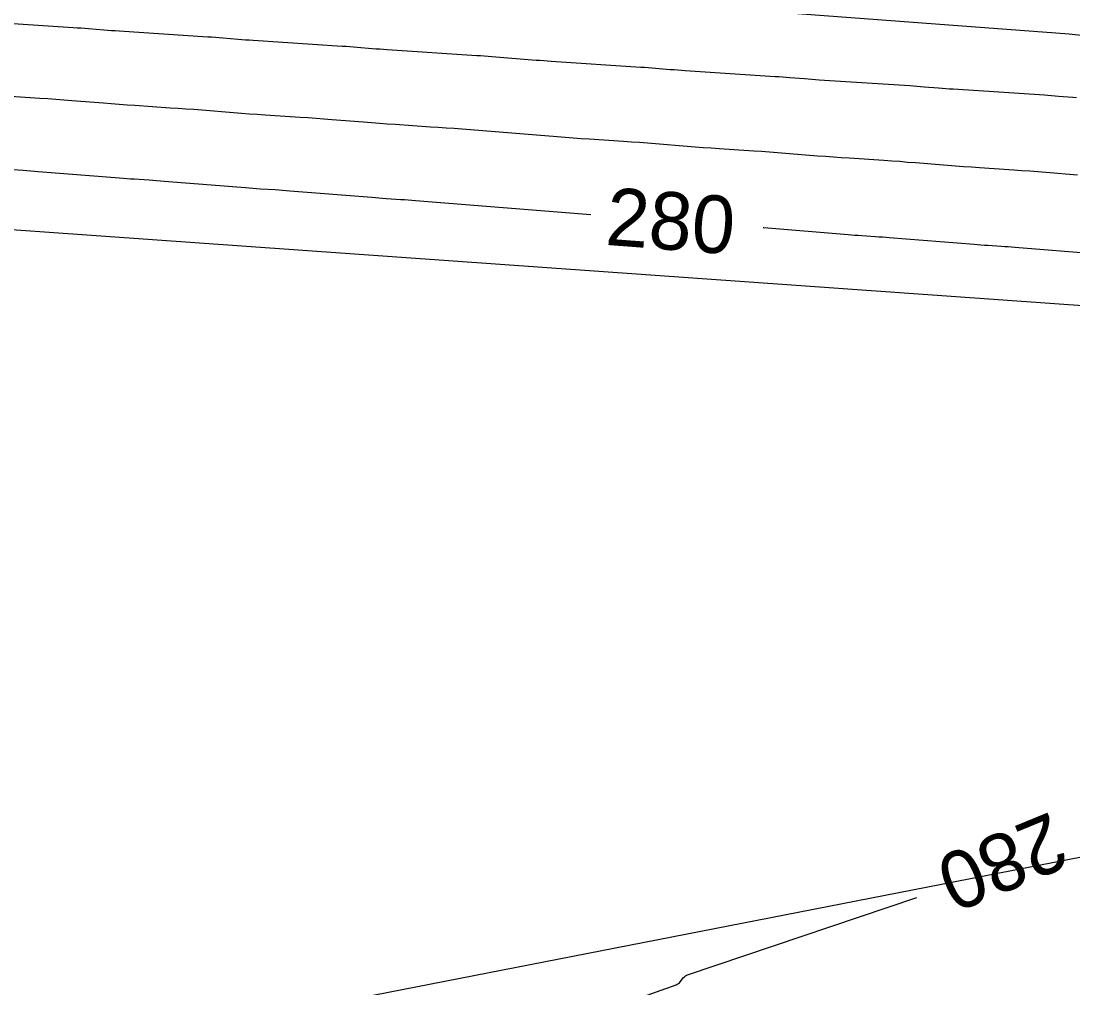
# Model space of a CAD drawing. Extents: x 1574966 to 1597594, y 720505 to 737840.
# Drawn here: x 1577690.4 to 1577800, y 724330.5 to 724431.3 of the extents above; entities that cross this region are included whole.
import ezdxf

# ---------------------------------------------------------------- set-up
doc = ezdxf.new("R2010")
doc.units = 0
for name, color, linetype in [('R_Contour Annot', 7, 'Continuous'), ('R_Contours', 7, 'Continuous'), ('S_BREAKLINE', 7, 'Continuous'), ('S_STREAM', 7, 'Continuous')]:
    doc.layers.add(name, color=color, linetype=linetype)

msp = doc.modelspace()

# ---------------------------------------------------------------- linework, layer by layer
at = {"layer": 'R_Contours'}
for points in [[(1577688.56, 724431.1), (1577695.86, 724430.62), (1577696.26, 724430.59), (1577696.66, 724430.56), (1577697.05, 724430.53), (1577697.45, 724430.5), (1577699.04, 724430.37), (1577699.43, 724430.34), (1577699.83, 724430.31), (1577700.23, 724430.28), (1577700.63, 724430.26), (1577709.87, 724429.65), (1577710.27, 724429.62), (1577710.66, 724429.59), (1577711.05, 724429.56), (1577711.44, 724429.53), (1577713.02, 724429.4), (1577713.41, 724429.37), (1577713.8, 724429.34), (1577714.2, 724429.32), (1577714.59, 724429.29), (1577723.89, 724428.67), (1577724.28, 724428.65), (1577724.67, 724428.62), (1577725.06, 724428.59), (1577725.45, 724428.56), (1577727, 724428.43), (1577727.39, 724428.4), (1577727.78, 724428.37), (1577728.17, 724428.35), (1577728.56, 724428.32), (1577737.91, 724427.7), (1577738.3, 724427.68), (1577738.68, 724427.65), (1577739.07, 724427.62), (1577739.45, 724427.59), (1577744.09, 724427.22), (1577744.48, 724427.19), (1577744.87, 724427.16), (1577745.26, 724427.13), (1577745.65, 724427.1), (1577754.99, 724426.49), (1577755.37, 724426.46), (1577755.76, 724426.43), (1577756.14, 724426.4), (1577756.53, 724426.37), (1577758.06, 724426.25), (1577758.45, 724426.22), (1577758.83, 724426.19), (1577759.22, 724426.16), (1577759.6, 724426.14), (1577769, 724425.52), (1577769.38, 724425.49), (1577769.76, 724425.47), (1577770.14, 724425.44), (1577770.52, 724425.41), (1577772.04, 724425.28), (1577772.42, 724425.25), (1577772.8, 724425.23), (1577773.18, 724425.2), (1577773.56, 724425.17), (1577783.01, 724424.55), (1577783.39, 724424.53), (1577783.76, 724424.5), (1577784.14, 724424.47), (1577784.52, 724424.44), (1577786.02, 724424.32), (1577786.4, 724424.29), (1577786.77, 724424.26), (1577787.15, 724424.23), (1577787.53, 724424.21), (1577797.04, 724423.58), (1577797.41, 724423.56), (1577797.78, 724423.53), (1577798.15, 724423.5), (1577798.52, 724423.47), (1577800.01, 724423.35), (1577800.38, 724423.33)], [(1577800.49, 724415.24), (1577797.18, 724415.51), (1577796.35, 724415.57), (1577795.52, 724415.63), (1577794.69, 724415.69), (1577793.86, 724415.75), (1577790.26, 724415.99), (1577789.43, 724416.04), (1577788.6, 724416.1), (1577787.77, 724416.16), (1577786.94, 724416.23), (1577783.62, 724416.5), (1577782.79, 724416.56), (1577781.96, 724416.63), (1577781.13, 724416.68), (1577780.3, 724416.74), (1577776.71, 724416.98), (1577775.88, 724417.03), (1577775.05, 724417.09), (1577774.22, 724417.16), (1577773.39, 724417.22), (1577770.07, 724417.49), (1577769.24, 724417.55), (1577768.41, 724417.62), (1577767.58, 724417.68), (1577766.75, 724417.73), (1577763.15, 724417.97), (1577762.32, 724418.02), (1577761.49, 724418.08), (1577760.66, 724418.15), (1577759.83, 724418.21), (1577756.51, 724418.48), (1577755.68, 724418.54), (1577754.85, 724418.61), (1577754.02, 724418.67), (1577753.19, 724418.72), (1577749.6, 724418.96), (1577748.77, 724419.02), (1577747.94, 724419.08), (1577747.11, 724419.14), (1577746.28, 724419.2), (1577736.36, 724420), (1577735.54, 724420.07), (1577734.72, 724420.13), (1577733.89, 724420.19), (1577733.07, 724420.24), (1577729.39, 724420.49), (1577728.57, 724420.54), (1577727.75, 724420.6), (1577726.92, 724420.66), (1577726.1, 724420.73), (1577722.81, 724420.99), (1577721.98, 724421.06), (1577721.16, 724421.12), (1577720.34, 724421.18), (1577719.51, 724421.23), (1577715.84, 724421.48), (1577715.01, 724421.53), (1577714.19, 724421.59), (1577713.37, 724421.65), (1577712.54, 724421.72), (1577709.25, 724421.98), (1577708.42, 724422.05), (1577707.6, 724422.11), (1577706.78, 724422.17), (1577705.95, 724422.22), (1577702.28, 724422.47), (1577701.46, 724422.52), (1577700.63, 724422.58), (1577699.81, 724422.64), (1577698.99, 724422.71), (1577695.69, 724422.97), (1577694.87, 724423.04), (1577694.04, 724423.1), (1577693.22, 724423.16), (1577692.39, 724423.22), (1577688.82, 724423.45)], [(1577749.79, 724411.08), (1577731.51, 724412.56), (1577731.13, 724412.59), (1577730.75, 724412.61), (1577730.37, 724412.64), (1577729.99, 724412.67), (1577728.47, 724412.77), (1577728.09, 724412.79), (1577727.71, 724412.82), (1577727.33, 724412.85), (1577726.95, 724412.88), (1577718.42, 724413.57), (1577718.03, 724413.6), (1577717.65, 724413.62), (1577717.27, 724413.65), (1577716.88, 724413.68), (1577715.34, 724413.78), (1577714.96, 724413.81), (1577714.58, 724413.83), (1577714.19, 724413.86), (1577713.81, 724413.89), (1577705.32, 724414.58), (1577704.93, 724414.61), (1577704.54, 724414.63), (1577704.15, 724414.66), (1577703.77, 724414.69), (1577702.21, 724414.79), (1577701.82, 724414.82), (1577701.44, 724414.85), (1577701.05, 724414.88), (1577700.66, 724414.91), (1577692.21, 724415.58), (1577691.82, 724415.62), (1577691.43, 724415.64), (1577691.03, 724415.67), (1577690.64, 724415.7), (1577689.07, 724415.8)], [(1577802.62, 724406.99), (1577793.96, 724407.69), (1577793.61, 724407.72), (1577793.26, 724407.74), (1577792.9, 724407.77), (1577792.55, 724407.79), (1577791.13, 724407.89), (1577790.78, 724407.91), (1577790.42, 724407.94), (1577790.07, 724407.96), (1577789.71, 724407.99), (1577780.88, 724408.7), (1577780.52, 724408.73), (1577780.16, 724408.76), (1577779.8, 724408.78), (1577779.45, 724408.81), (1577778.01, 724408.9), (1577777.65, 724408.93), (1577777.29, 724408.95), (1577776.93, 724408.98), (1577776.58, 724409.01), (1577767.79, 724409.72), (1577767.74, 724409.72)], [(1577745.41, 724326.14), (1577758.67, 724330.87), (1577758.79, 724330.93), (1577758.91, 724330.99), (1577759.01, 724331.08), (1577759.1, 724331.18), (1577759.44, 724331.61), (1577759.53, 724331.71), (1577759.63, 724331.79), (1577759.74, 724331.86), (1577759.86, 724331.91), (1577783.76, 724339.96)]]:
    msp.add_lwpolyline(points, dxfattribs=at)
at = {"layer": 'S_BREAKLINE'}
for p, q in [((1577881.29, 724395.93), (1577676.48, 724410.43)), ((1577807.3, 724345.41), (1577672.47, 724319.11))]:
    msp.add_line(p, q, dxfattribs=at)
at = {"layer": 'S_STREAM'}
for p, q in [((1577684.72, 724438.57), (1577799.62, 724429.96)), ((1577799.62, 724429.96), (1577834.83, 724425.99))]:
    msp.add_line(p, q, dxfattribs=at)

# ---------------------------------------------------------------- texts
at = {"layer": 'R_Contour Annot'}
for rotation, p in [(355.663, (1577751.21, 724407.97)), (202.3892, (1577797.73, 724348.96))]:
    msp.add_text('280', height=6, rotation=rotation, dxfattribs=at).set_placement(p)

doc.saveas('drawing.dxf')
